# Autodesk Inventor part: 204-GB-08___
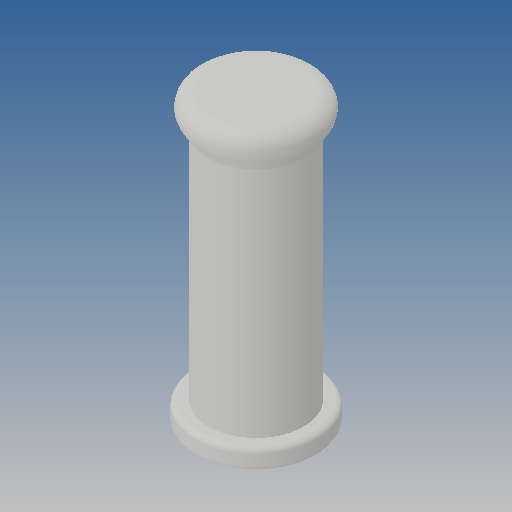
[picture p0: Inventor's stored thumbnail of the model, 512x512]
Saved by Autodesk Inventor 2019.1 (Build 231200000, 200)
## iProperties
Created: 2012-09
Part Number: 204-GB-08___
Material: Ogólny
Document SubType Name: Modeling
Designer: CADENGINEERING4
Density: 1 g/cm^3
Appearance: Domyślna
Author: CADENGINEERING4
Revision Number: ÈÎºÎ
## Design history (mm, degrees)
feature "NONE"
node "Bryła1"
